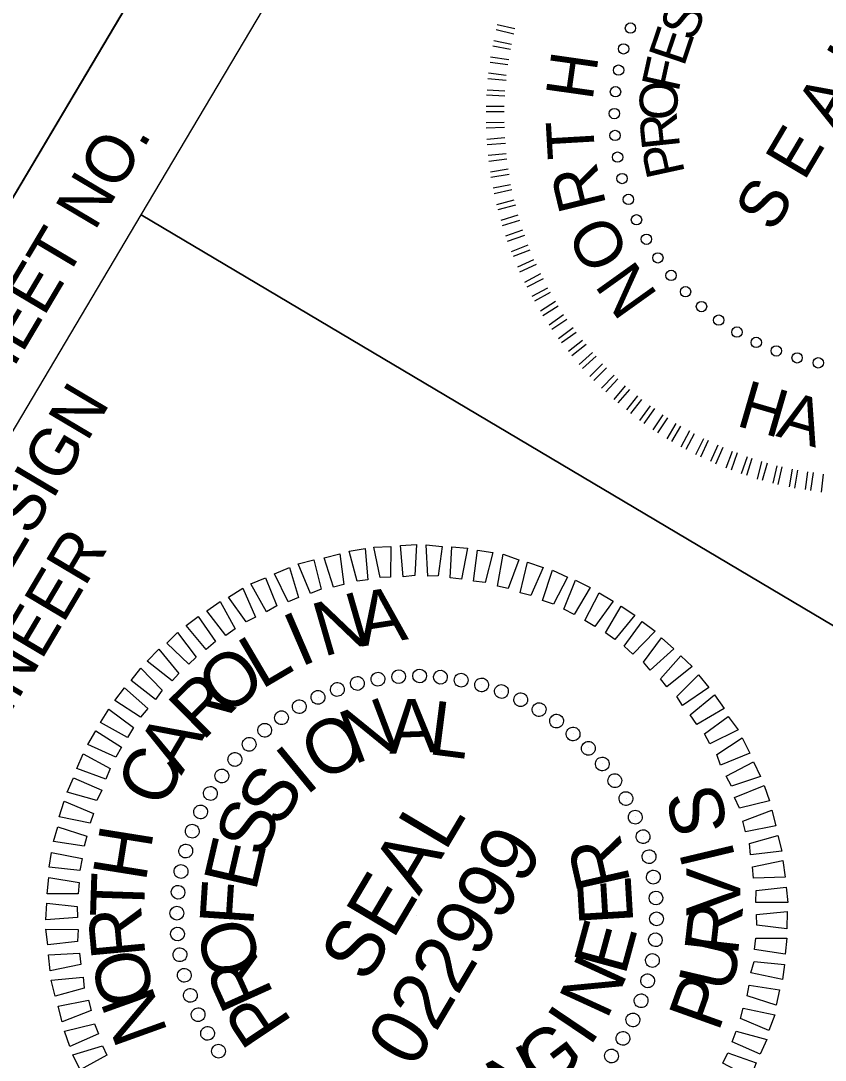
# Model space of a CAD drawing. Extents: x 2138768 to 2143723, y 406633 to 414335.
# Drawn here: x 2141770.8 to 2141855.1, y 412025.2 to 412134 of the extents above; entities that cross this region are included whole.
import ezdxf

# ---------------------------------------------------------------- set-up
doc = ezdxf.new("R2010")
doc.units = 0
for name, color, linetype in [('Prop SBG', 7, 'Continuous'), ('Sheet Plan And Profile CELL', 7, 'Continuous'), ('Sheet Sticker Exception Certification CELL', 7, 'Continuous'), ('Sheet Sticker Preliminary CELL', 7, 'Continuous')]:
    doc.layers.add(name, color=color, linetype=linetype)

msp = doc.modelspace()

# ---------------------------------------------------------------- linework, layer by layer
at = {"layer": 'Prop SBG'}
for p, q in [((2141812.65, 412065.43), (2141812.65, 412065.43)), ((2141806.12, 412064.65), (2141806.12, 412064.65)), ((2141808.27, 412065.12), (2141808.27, 412065.12)), ((2141810.4, 412065.37), (2141810.4, 412065.37)), ((2141814.8, 412065.32), (2141814.8, 412065.32)), ((2141816.95, 412065.03), (2141816.95, 412065.03)), ((2141819.1, 412064.52), (2141819.1, 412064.52)), ((2141804.01, 412064.03), (2141804.01, 412064.03)), ((2141821.22, 412063.78), (2141821.22, 412063.78)), ((2141800.01, 412062.21), (2141800.01, 412062.21)), ((2141801.99, 412063.19), (2141801.99, 412063.19)), ((2141823.18, 412062.97), (2141823.18, 412062.97)), ((2141798.16, 412061.04), (2141798.16, 412061.04)), ((2141825.13, 412061.93), (2141825.13, 412061.93)), ((2141826.98, 412060.72), (2141826.98, 412060.72)), ((2141796.36, 412059.78), (2141796.36, 412059.78)), ((2141828.72, 412059.33), (2141828.72, 412059.33)), ((2141794.77, 412058.28), (2141794.77, 412058.28)), ((2141830.3, 412057.87), (2141830.3, 412057.87)), ((2141793.24, 412056.68), (2141793.24, 412056.68)), ((2141831.77, 412056.24), (2141831.77, 412056.24)), ((2141791.88, 412054.98), (2141791.88, 412054.98)), ((2141833.06, 412054.48), (2141833.06, 412054.48)), ((2141790.67, 412053.14), (2141790.67, 412053.14)), ((2141834.27, 412052.6), (2141834.27, 412052.6)), ((2141789.63, 412051.19), (2141789.63, 412051.19)), ((2141835.21, 412050.64), (2141835.21, 412050.64)), ((2141788.79, 412049.18), (2141788.79, 412049.18)), ((2141836.1, 412048.6), (2141836.1, 412048.6)), ((2141788.12, 412047.08), (2141788.12, 412047.08)), ((2141836.71, 412046.49), (2141836.71, 412046.49)), ((2141787.56, 412044.96), (2141787.56, 412044.96)), ((2141837.18, 412044.34), (2141837.18, 412044.34)), ((2141787.31, 412042.78), (2141787.31, 412042.78)), ((2141837.41, 412042.17), (2141837.41, 412042.17)), ((2141787.18, 412040.58), (2141787.18, 412040.58)), ((2141812.29, 412040.3), (2141812.29, 412040.3)), ((2141837.5, 412039.96), (2141837.5, 412039.96)), ((2141787.27, 412038.38), (2141787.27, 412038.38)), ((2141837.36, 412037.77), (2141837.36, 412037.77)), ((2141787.49, 412036.2), (2141787.49, 412036.2)), ((2141837.03, 412035.64), (2141837.03, 412035.64)), ((2141787.96, 412034.06), (2141787.96, 412034.06)), ((2141836.56, 412033.47), (2141836.56, 412033.47)), ((2141788.58, 412031.95), (2141788.58, 412031.95)), ((2141835.8, 412031.42), (2141835.8, 412031.42)), ((2141789.38, 412029.96), (2141789.38, 412029.96)), ((2141834.96, 412029.41), (2141834.96, 412029.41)), ((2141790.4, 412027.95), (2141790.4, 412027.95)), ((2141833.92, 412027.46), (2141833.92, 412027.46)), ((2141791.53, 412026.12), (2141791.53, 412026.12)), ((2141832.71, 412025.62), (2141832.71, 412025.62))]:
    msp.add_line(p, q, dxfattribs=at)
for points in [[(2141806.06, 412075.34), (2141805.23, 412078.46), (2141806.91, 412078.74), (2141807.19, 412075.49)], [(2141808.49, 412075.71), (2141807.82, 412078.9), (2141809.6, 412078.95), (2141809.57, 412075.76)], [(2141810.88, 412075.8), (2141810.6, 412079.06), (2141812.29, 412079.16), (2141812.12, 412075.94)], [(2141813.47, 412075.84), (2141813.32, 412079.13), (2141814.97, 412078.97), (2141814.55, 412075.9)], [(2141815.81, 412075.67), (2141816, 412078.94), (2141817.65, 412078.78), (2141817.02, 412075.54)], [(2141818.28, 412075.32), (2141818.69, 412078.57), (2141820.29, 412078.32), (2141819.48, 412075.18)], [(2141801.2, 412074.03), (2141799.9, 412077.14), (2141801.55, 412077.56), (2141802.29, 412074.49)], [(2141803.59, 412074.71), (2141802.62, 412077.79), (2141804.27, 412078.21), (2141804.69, 412074.99)], [(2141820.78, 412074.82), (2141821.36, 412078.15), (2141823, 412077.58), (2141821.91, 412074.56)], [(2141798.83, 412073.17), (2141797.42, 412076.1), (2141798.97, 412076.75), (2141799.92, 412073.63)], [(2141823.16, 412074.11), (2141823.91, 412077.34), (2141825.55, 412076.77), (2141824.28, 412073.85)], [(2141825.48, 412073.31), (2141826.54, 412076.47), (2141828.11, 412075.77), (2141826.64, 412072.92)], [(2141796.57, 412072.12), (2141794.94, 412075.07), (2141796.47, 412075.68), (2141797.65, 412072.76)], [(2141827.73, 412072.39), (2141828.96, 412075.44), (2141830.47, 412074.66), (2141828.81, 412071.86)], [(2141794.43, 412071.06), (2141792.6, 412073.66), (2141794.08, 412074.59), (2141795.43, 412071.57)], [(2141829.93, 412071.2), (2141831.42, 412074.1), (2141832.89, 412073.23), (2141830.97, 412070.58)], [(2141792.31, 412069.64), (2141790.34, 412072.21), (2141791.73, 412073.19), (2141793.3, 412070.33)], [(2141832.09, 412069.92), (2141833.75, 412072.72), (2141835.16, 412071.76), (2141833.07, 412069.22)], [(2141790.27, 412068.17), (2141788.16, 412070.7), (2141789.42, 412071.65), (2141791.23, 412069)], [(2141834.05, 412068.52), (2141835.95, 412071.12), (2141837.31, 412070.08), (2141834.96, 412067.69)], [(2141788.43, 412066.64), (2141786.12, 412068.83), (2141787.25, 412069.96), (2141789.22, 412067.39)], [(2141836.09, 412066.84), (2141837.96, 412069.4), (2141839.24, 412068.23), (2141836.77, 412066.03)], [(2141786.68, 412064.88), (2141784.07, 412066.96), (2141785.28, 412068.22), (2141787.39, 412065.68)], [(2141837.85, 412065.1), (2141839.98, 412067.51), (2141841.18, 412066.39), (2141838.53, 412064.28)], [(2141784.95, 412062.94), (2141782.4, 412064.92), (2141783.41, 412066.24), (2141785.65, 412063.92)], [(2141839.56, 412063.27), (2141841.83, 412065.53), (2141842.91, 412064.19), (2141840.17, 412062.33)], [(2141783.38, 412061.08), (2141780.7, 412062.84), (2141781.71, 412064.16), (2141784.16, 412062.01)], [(2141840.97, 412061.32), (2141843.5, 412063.43), (2141844.52, 412062.01), (2141841.66, 412060.33)], [(2141782.01, 412058.97), (2141779.2, 412060.52), (2141780.05, 412061.94), (2141782.63, 412060.01)], [(2141842.47, 412059.33), (2141844.96, 412061.17), (2141845.98, 412059.75), (2141843.02, 412058.3)], [(2141780.78, 412056.9), (2141777.85, 412058.24), (2141778.69, 412059.66), (2141781.4, 412057.94)], [(2141843.75, 412057.17), (2141846.41, 412058.91), (2141847.22, 412057.32), (2141844.14, 412056.06)], [(2141779.76, 412054.6), (2141776.7, 412055.72), (2141777.37, 412057.24), (2141780.21, 412055.73)], [(2141844.73, 412054.9), (2141847.6, 412056.4), (2141848.32, 412054.86), (2141845.28, 412053.87)], [(2141778.8, 412052.38), (2141775.69, 412053.23), (2141776.36, 412054.75), (2141779.32, 412053.46)], [(2141845.62, 412052.68), (2141848.7, 412053.94), (2141849.26, 412052.32), (2141846.13, 412051.56)], [(2141778.09, 412050), (2141774.85, 412050.64), (2141775.38, 412052.31), (2141778.45, 412051.01)], [(2141846.48, 412050.19), (2141849.51, 412051.36), (2141849.93, 412049.72), (2141846.76, 412049.09)], [(2141777.46, 412047.57), (2141774.26, 412048.07), (2141774.71, 412049.61), (2141777.74, 412048.63)], [(2141847.19, 412047.85), (2141850.15, 412048.71), (2141850.57, 412047.06), (2141847.3, 412046.67)], [(2141777.01, 412045.05), (2141773.82, 412045.37), (2141774.04, 412046.92), (2141777.28, 412046.28)], [(2141847.48, 412045.4), (2141850.67, 412046.07), (2141850.93, 412044.34), (2141847.6, 412044.22)], [(2141776.83, 412042.59), (2141773.58, 412042.6), (2141773.76, 412044.29), (2141776.96, 412043.79)], [(2141847.89, 412042.94), (2141851.01, 412043.3), (2141851.21, 412041.67), (2141847.84, 412041.69)], [(2141776.77, 412040.12), (2141773.47, 412039.87), (2141773.57, 412041.61), (2141776.74, 412041.25)], [(2141847.91, 412040.43), (2141851.12, 412040.73), (2141851.1, 412038.94), (2141847.94, 412039.3)], [(2141776.79, 412037.6), (2141773.66, 412037.25), (2141773.46, 412038.88), (2141776.83, 412038.86)], [(2141847.84, 412037.96), (2141851.1, 412037.95), (2141850.91, 412036.26), (2141847.71, 412036.76)], [(2141777.11, 412035.2), (2141773.91, 412034.53), (2141773.74, 412036.21), (2141776.99, 412036.38)], [(2141847.67, 412035.5), (2141850.85, 412035.18), (2141850.63, 412033.63), (2141847.31, 412034.31)], [(2141777.49, 412032.7), (2141774.44, 412031.89), (2141774.02, 412033.54), (2141777.37, 412033.88)], [(2141847.13, 412033.02), (2141850.33, 412032.52), (2141849.96, 412030.93), (2141846.93, 412031.92)], [(2141778.2, 412030.36), (2141775.17, 412029.18), (2141774.75, 412030.83), (2141777.92, 412031.46)], [(2141846.5, 412030.6), (2141849.82, 412029.91), (2141849.21, 412028.29), (2141846.22, 412029.54)], [(2141778.96, 412027.92), (2141775.97, 412026.61), (2141775.41, 412028.22), (2141778.55, 412028.99)], [(2141845.79, 412028.22), (2141848.98, 412027.32), (2141848.31, 412025.8), (2141845.35, 412027.09)], [(2141779.86, 412025.7), (2141777.07, 412024.15), (2141776.27, 412025.74), (2141779.39, 412026.68)], [(2141844.91, 412025.95), (2141847.89, 412024.88), (2141847.3, 412023.31), (2141844.38, 412024.87)]]:
    msp.add_lwpolyline(points, close=True, dxfattribs=at)
for centre, major_axis in [((2141806.1, 412064.62), (-0.178, 0.699)), ((2141808.25, 412065.07), (-0.117, 0.712)), ((2141810.42, 412065.33), (-0.054, 0.719)), ((2141812.62, 412065.4), (0.009, 0.721)), ((2141814.8, 412065.28), (0.072, 0.718)), ((2141816.97, 412064.97), (0.134, 0.709)), ((2141804, 412063.99), (-0.239, 0.681)), ((2141819.11, 412064.47), (0.195, 0.695)), ((2141821.19, 412063.78), (0.255, 0.675)), ((2141801.97, 412063.17), (-0.297, 0.657)), ((2141823.21, 412062.92), (0.313, 0.65)), ((2141800.01, 412062.19), (-0.353, 0.629)), ((2141825.14, 412061.88), (0.368, 0.62)), ((2141798.15, 412061.03), (-0.407, 0.596)), ((2141826.97, 412060.68), (0.421, 0.586)), ((2141796.39, 412059.72), (-0.457, 0.558)), ((2141828.7, 412059.33), (0.47, 0.547)), ((2141794.76, 412058.25), (-0.504, 0.516)), ((2141830.3, 412057.83), (0.516, 0.504)), ((2141793.26, 412056.66), (-0.547, 0.47)), ((2141831.76, 412056.19), (0.558, 0.457)), ((2141791.9, 412054.93), (-0.586, 0.421)), ((2141833.07, 412054.44), (0.596, 0.407)), ((2141790.7, 412053.1), (-0.62, 0.368)), ((2141834.23, 412052.57), (0.629, 0.353)), ((2141789.67, 412051.17), (-0.65, 0.313)), ((2141835.21, 412050.62), (0.657, 0.297)), ((2141788.8, 412049.15), (-0.675, 0.255)), ((2141836.03, 412048.58), (0.681, 0.239)), ((2141788.12, 412047.07), (-0.695, 0.195)), ((2141836.66, 412046.48), (0.699, 0.178)), ((2141787.62, 412044.93), (-0.709, 0.134)), ((2141837.11, 412044.34), (0.712, 0.117)), ((2141787.31, 412042.76), (-0.718, 0.072)), ((2141837.37, 412042.16), (0.719, 0.054)), ((2141787.18, 412040.57), (-0.721, 0.009)), ((2141837.44, 412039.97), (0.721, -0.009)), ((2141787.25, 412038.38), (-0.719, -0.054)), ((2141837.32, 412037.78), (0.718, -0.072)), ((2141787.51, 412036.21), (-0.712, -0.117)), ((2141837.01, 412035.61), (0.709, -0.134)), ((2141787.96, 412034.06), (-0.699, -0.178)), ((2141836.51, 412033.48), (0.695, -0.195)), ((2141788.6, 412031.96), (-0.681, -0.239)), ((2141835.82, 412031.39), (0.675, -0.255)), ((2141789.41, 412029.93), (-0.657, -0.297)), ((2141834.96, 412029.38), (0.65, -0.313)), ((2141790.4, 412027.97), (-0.629, -0.353)), ((2141833.92, 412027.45), (0.62, -0.368)), ((2141791.55, 412026.11), (-0.596, -0.407)), ((2141832.72, 412025.61), (0.586, -0.421))]:
    msp.add_ellipse(centre, major_axis=major_axis, ratio=0.999708, dxfattribs=at)
at = {"layer": 'Sheet Plan And Profile CELL'}
for p, q in [((2141721.64, 412034.04), (2141823.75, 412206.07)), ((2141783.46, 412113.69), (2141880.16, 412056.3))]:
    msp.add_line(p, q, dxfattribs=at)
for points in [[(2141700.1, 412046.82), (2141802.21, 412218.85), (2141823.75, 412206.07), (2141721.64, 412034.04)], [(2141783.46, 412113.69), (2141834.5, 412199.69), (2141931.24, 412142.27), (2141880.2, 412056.27)], [(2141732.39, 412027.66), (2141783.46, 412113.69), (2141880.2, 412056.27), (2141829.13, 411970.24)]]:
    msp.add_lwpolyline(points, close=True, dxfattribs=at)
at = {"layer": 'Sheet Sticker Preliminary CELL'}
for p, q in [((2141822.49, 412132.63), (2141820.63, 412133.06)), ((2141822.59, 412133.18), (2141820.73, 412133.61)), ((2141822.24, 412131.55), (2141820.4, 412131.92)), ((2141822.13, 412131), (2141820.29, 412131.37)), ((2141821.85, 412129.39), (2141820, 412129.65)), ((2141821.95, 412129.94), (2141820.06, 412130.22)), ((2141821.7, 412128.3), (2141819.83, 412128.52)), ((2141821.67, 412127.77), (2141819.77, 412127.95)), ((2141821.56, 412126.66), (2141819.68, 412126.77)), ((2141821.53, 412126.12), (2141819.64, 412126.24)), ((2141821.49, 412125.03), (2141819.6, 412125.04)), ((2141821.49, 412124.47), (2141819.6, 412124.48)), ((2141821.46, 412123.38), (2141819.58, 412123.32)), ((2141821.52, 412122.84), (2141819.59, 412122.76)), ((2141821.55, 412121.76), (2141819.67, 412121.6)), ((2141821.6, 412121.18), (2141819.68, 412121.04)), ((2141821.67, 412120.08), (2141819.79, 412119.91)), ((2141821.74, 412119.53), (2141819.87, 412119.3)), ((2141821.9, 412118.49), (2141820.03, 412118.15)), ((2141822.01, 412117.93), (2141820.09, 412117.61)), ((2141822.14, 412116.84), (2141820.31, 412116.48)), ((2141822.28, 412116.32), (2141820.42, 412115.91)), ((2141822.48, 412115.25), (2141820.68, 412114.76)), ((2141822.66, 412114.7), (2141820.82, 412114.23)), ((2141822.92, 412113.65), (2141821.14, 412113.09)), ((2141823.1, 412113.1), (2141821.28, 412112.56)), ((2141823.39, 412112.09), (2141821.63, 412111.46)), ((2141823.61, 412111.52), (2141821.8, 412110.92)), ((2141823.97, 412110.52), (2141822.22, 412109.83)), ((2141824.17, 412110.01), (2141822.42, 412109.32)), ((2141824.56, 412109), (2141822.88, 412108.22)), ((2141824.83, 412108.51), (2141823.08, 412107.71)), ((2141825.3, 412107.51), (2141823.6, 412106.62)), ((2141825.56, 412107.01), (2141823.86, 412106.13)), ((2141826.03, 412106.01), (2141824.39, 412105.14)), ((2141826.31, 412105.56), (2141824.66, 412104.65)), ((2141826.87, 412104.62), (2141825.27, 412103.62)), ((2141827.14, 412104.13), (2141825.54, 412103.13)), ((2141827.71, 412103.23), (2141826.18, 412102.14)), ((2141828.05, 412102.75), (2141826.46, 412101.69)), ((2141828.69, 412101.87), (2141827.17, 412100.71)), ((2141829.02, 412101.39), (2141827.48, 412100.3)), ((2141829.69, 412100.55), (2141828.21, 412099.37)), ((2141830.05, 412100.12), (2141828.57, 412098.93)), ((2141830.72, 412099.27), (2141829.32, 412098.04)), ((2141831.1, 412098.88), (2141829.67, 412097.61)), ((2141831.79, 412098.08), (2141830.45, 412096.76)), ((2141832.21, 412097.66), (2141830.87, 412096.34)), ((2141833, 412096.92), (2141831.67, 412095.53)), ((2141833.38, 412096.53), (2141832.12, 412095.16)), ((2141834.16, 412095.78), (2141832.98, 412094.36)), ((2141834.6, 412095.41), (2141833.39, 412094.01)), ((2141835.44, 412094.74), (2141834.28, 412093.26)), ((2141835.88, 412094.37), (2141834.72, 412092.88)), ((2141836.76, 412093.68), (2141835.64, 412092.17)), ((2141837.21, 412093.41), (2141836.11, 412091.84)), ((2141838.11, 412092.77), (2141837.05, 412091.17)), ((2141838.58, 412092.43), (2141837.54, 412090.88)), ((2141839.46, 412091.85), (2141838.51, 412090.25)), ((2141839.96, 412091.56), (2141839, 412089.95)), ((2141840.89, 412091.06), (2141839.99, 412089.37)), ((2141841.38, 412090.77), (2141840.51, 412089.11)), ((2141842.35, 412090.25), (2141841.52, 412088.57)), ((2141842.86, 412090.06), (2141842.04, 412088.32)), ((2141843.85, 412089.58), (2141843.1, 412087.85)), ((2141844.37, 412089.33), (2141843.62, 412087.6)), ((2141845.35, 412088.92), (2141844.71, 412087.18)), ((2141845.88, 412088.77), (2141845.25, 412086.97)), ((2141846.92, 412088.37), (2141846.3, 412086.57)), ((2141847.42, 412088.19), (2141846.87, 412086.4)), ((2141848.45, 412087.85), (2141847.98, 412086.02)), ((2141849.02, 412087.68), (2141848.5, 412085.87)), ((2141850.03, 412087.42), (2141849.62, 412085.6)), ((2141850.58, 412087.31), (2141850.15, 412085.46)), ((2141851.66, 412087.06), (2141851.33, 412085.2)), ((2141852.21, 412086.96), (2141851.88, 412085.09)), ((2141853.27, 412086.78), (2141853.01, 412084.93)), ((2141853.85, 412086.71), (2141853.56, 412084.82)), ((2141854.91, 412086.53), (2141854.69, 412084.65))]:
    msp.add_line(p, q, dxfattribs=at)
for centre in [(2141834.71, 412133.26), (2141833.99, 412131.08), (2141833.47, 412128.85), (2141833.14, 412126.59), (2141833.02, 412124.3), (2141833.09, 412122.01), (2141833.36, 412119.74), (2141833.83, 412117.5), (2141834.49, 412115.31), (2141835.34, 412113.18), (2141836.38, 412111.14), (2141837.58, 412109.19), (2141838.96, 412107.36), (2141840.48, 412105.65), (2141842.15, 412104.09), (2141843.95, 412102.67), (2141845.87, 412101.42), (2141847.89, 412100.34), (2141849.99, 412099.44), (2141852.17, 412098.72), (2141854.39, 412098.2)]:
    msp.add_circle(centre, 0.543, dxfattribs=at)

# ---------------------------------------------------------------- texts
at = {"layer": 'Prop SBG'}
for s, height, rotation, p in [('N', 5.65, 16.1282, (2141802.5, 412067.38)), ('A', 5.65, 8.9264, (2141806.53, 412068.48)), ('I', 5.65, 23.3294, (2141800.11, 412066.29)), ('L', 5.65, 30.5301, (2141796.03, 412063.94)), ('O', 5.65, 37.7304, (2141792.2, 412061.02)), ('R', 5.65, 44.9304, (2141789.88, 412058.49)), ('N', 5.65, 20.7859, (2141805.71, 412056.09)), ('A', 5.65, 2.0695, (2141809.43, 412057.26)), ('L', 5.65, 352.7101, (2141813.38, 412057.25)), ('A', 5.65, 59.3296, (2141787.65, 412054.93)), ('O', 5.65, 30.1427, (2141802.36, 412054.18)), ('C', 5.65, 66.5291, (2141785.89, 412051.37)), ('I', 5.65, 39.4989, (2141800.7, 412052.77)), ('S', 5.65, 58.2097, (2141797.99, 412049.37)), ('S', 5.65, 103.3787, (2141845.01, 412049.4)), ('S', 5.65, 67.5649, (2141796.23, 412046.22)), ('SEAL', 6.01, 59.3093, (2141807.08, 412033.08)), ('H', 5.65, 80.9287, (2141783.92, 412043.74)), ('022999', 6.012, 59.3093, (2141812.02, 412024.14)), ('E', 5.65, 76.9203, (2141795.44, 412042.73)), ('R', 5.65, 102.7907, (2141834.74, 412043.76)), ('I', 5.65, 103.3787, (2141845.73, 412046.3)), ('V', 5.65, 90.1548, (2141846.21, 412040.29)), ('T', 5.65, 88.129, (2141783.73, 412040.07)), ('F', 5.65, 86.2763, (2141795.18, 412039.15)), ('E', 5.65, 93.4333, (2141835.02, 412039.51)), ('R', 5.65, 95.3298, (2141783.91, 412036.06)), ('R', 5.65, 83.5428, (2141845.94, 412036)), ('O', 5.65, 104.9905, (2141796.11, 412034.82)), ('E', 5.65, 74.721, (2141834.14, 412033.92)), ('U', 5.65, 76.9308, (2141845.18, 412032.07)), ('O', 5.65, 102.531, (2141784.93, 412031.49)), ('R', 5.65, 114.3489, (2141797.39, 412032.07)), ('N', 5.65, 65.3656, (2141832.21, 412029.29)), ('P', 5.65, 70.3188, (2141843.91, 412028)), ('N', 5.65, 109.7328, (2141786.28, 412028.07)), ('P', 5.65, 123.7081, (2141799.36, 412029.1)), ('I', 5.65, 56.0105, (2141830.41, 412026.46)), ('G', 5.65, 37.2995, (2141825.49, 412021.69)), ('N', 5.65, 27.9432, (2141821.62, 412019.5))]:
    msp.add_text(s, height=height, rotation=rotation, dxfattribs=at).set_placement(p)
at = {"layer": 'Sheet Plan And Profile CELL'}
for s, height, p in [('R/W SHEET NO.', 5.0001, (2141758.65, 412078.36)), ('ROADWAY DESIGN', 5.0001, (2141748.57, 412040.62)), ('ENGINEER', 5, (2141762.18, 412048.76))]:
    msp.add_text(s, height=height, rotation=59.3093, dxfattribs=at).set_placement(p)
at = {"layer": 'Sheet Sticker Exception Certification CELL'}
for s, p in [('DOCUMENT NOT CONSIDERED FINAL', (2141848.78, 411983.08)), ('UNLESS ALL SIGNATURES COMPLETED', (2141853.76, 411974.22))]:
    msp.add_text(s, height=5.5, rotation=59.3093, dxfattribs=at).set_placement(p)
at = {"layer": 'Sheet Sticker Preliminary CELL'}
for s, height, rotation, p in [('S', 3.98, 65.1598, (2141841.22, 412131.71)), ('E', 3.98, 71.3437, (2141840.3, 412129.13)), ('S E A L', 4.98, 59.3093, (2141849.69, 412111.72)), ('H', 4.96, 81.9245, (2141830.72, 412125.57)), ('F', 3.98, 77.5277, (2141839.72, 412126.46)), ('O', 3.98, 89.8955, (2141839.65, 412123.61)), ('R', 3.98, 96.0794, (2141839.92, 412120.78)), ('T', 4.96, 93.2995, (2141831.01, 412119.66)), ('P', 3.98, 102.2633, (2141840.43, 412118.08)), ('R', 4.96, 103.721, (2141832.2, 412114.72)), ('O', 4.96, 118.252, (2141834.74, 412109.53)), ('N', 4.96, 125.5175, (2141837.68, 412105.28)), ('H', 4.98, 343.7672, (2141845.65, 412091.65)), ('A', 4.98, 343.7672, (2141849.86, 412090.55))]:
    msp.add_text(s, height=height, rotation=rotation, dxfattribs=at).set_placement(p)

doc.saveas('drawing.dxf')
